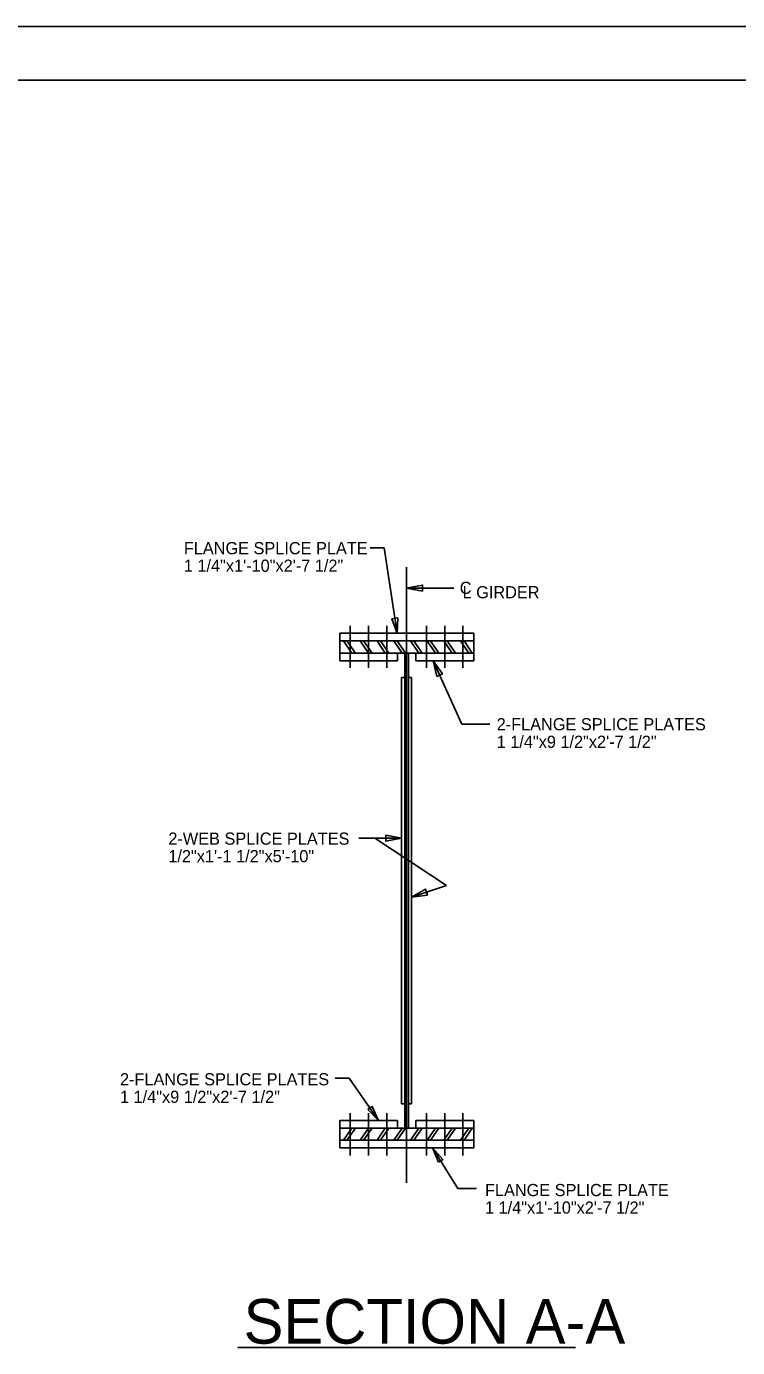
# Model space of a CAD drawing. Extents: x 1970675.2 to 1970715, y 796143 to 796167.2.
# Drawn here: x 1970685.62 to 1970692.92, y 796153.69 to 796167.25 of the extents above; entities that cross this region are included whole.
import ezdxf

# ---------------------------------------------------------------- set-up
doc = ezdxf.new("R2010")
doc.units = 0
for name, color, linetype in [('BR_AUTO DIMENSION', 7, 'Continuous'), ('BR_BORDER LINES', 7, 'Continuous'), ('BR_CENTER LINES', 7, 'Continuous'), ('BR_STRUCTURAL STEEL', 7, 'Continuous'), ('BR_TEXT', 7, 'Continuous'), ('Level 31', 7, 'Continuous')]:
    doc.layers.add(name, color=color, linetype=linetype)

msp = doc.modelspace()

# ---------------------------------------------------------------- linework, layer by layer
at = {"layer": 'BR_AUTO DIMENSION'}
for p, q in [((1970689.15, 796161.895), (1970689.296, 796161.895)), ((1970689.296, 796161.895), (1970689.428, 796161.018)), ((1970690.091, 796160.085), (1970689.798, 796160.736)), ((1970690.377, 796160.085), (1970690.091, 796160.085)), ((1970689.034, 796158.915), (1970689.474, 796158.915)), ((1970689.2, 796158.915), (1970689.934, 796158.429)), ((1970689.934, 796158.429), (1970689.576, 796158.31)), ((1970688.791, 796156.451), (1970688.937, 796156.451)), ((1970688.937, 796156.451), (1970689.238, 796156.018)), ((1970690.05, 796155.32), (1970689.791, 796155.736)), ((1970690.242, 796155.32), (1970690.05, 796155.32))]:
    msp.add_line(p, q, dxfattribs=at)
for points in [[(1970689.688, 796161.449), (1970689.525, 796161.48), (1970689.688, 796161.512)], [(1970689.434, 796161.176), (1970689.428, 796161.018), (1970689.374, 796161.167)], [(1970689.836, 796160.575), (1970689.798, 796160.736), (1970689.893, 796160.601)], [(1970689.312, 796158.946), (1970689.474, 796158.915), (1970689.312, 796158.884)], [(1970689.74, 796158.331), (1970689.576, 796158.31), (1970689.72, 796158.391)], [(1970689.128, 796156.131), (1970689.17, 796156.161), (1970689.238, 796156.018)], [(1970689.852, 796155.59), (1970689.896, 796155.617), (1970689.791, 796155.736)]]:
    msp.add_lwpolyline(points, close=True, dxfattribs=at)
msp.add_lwpolyline([(1970689.525, 796161.48), (1970690.011, 796161.48)], dxfattribs=at)
at = {"layer": 'BR_BORDER LINES'}
msp.add_line((1970714.286, 796166.696), (1970677.253, 796166.696), dxfattribs=at)
at = {"layer": 'BR_CENTER LINES'}
msp.add_line((1970689.525, 796161.698), (1970689.525, 796155.379), dxfattribs=at)
at = {"layer": 'BR_STRUCTURAL STEEL'}
for p, q in [((1970688.838, 796161.018), (1970690.213, 796161.018)), ((1970688.838, 796160.94), (1970688.838, 796161.018)), ((1970688.947, 796160.663), (1970688.947, 796161.095)), ((1970689.135, 796160.663), (1970689.135, 796161.095)), ((1970689.322, 796160.663), (1970689.322, 796161.095)), ((1970689.728, 796160.663), (1970689.728, 796161.095)), ((1970689.916, 796160.663), (1970689.916, 796161.095)), ((1970690.103, 796160.663), (1970690.103, 796161.095)), ((1970690.213, 796161.018), (1970690.213, 796160.94)), ((1970688.838, 796160.815), (1970688.838, 796160.94)), ((1970690.213, 796160.94), (1970688.838, 796160.94)), ((1970688.838, 796160.94), (1970690.213, 796160.94)), ((1970688.878, 796160.94), (1970688.963, 796160.815)), ((1970688.913, 796160.94), (1970688.999, 796160.815)), ((1970689.049, 796160.94), (1970689.135, 796160.815)), ((1970689.084, 796160.94), (1970689.17, 796160.815)), ((1970689.221, 796160.94), (1970689.306, 796160.815)), ((1970689.256, 796160.94), (1970689.342, 796160.815)), ((1970689.392, 796160.94), (1970689.478, 796160.815)), ((1970689.427, 796160.94), (1970689.513, 796160.815)), ((1970689.563, 796160.94), (1970689.649, 796160.815)), ((1970689.599, 796160.94), (1970689.684, 796160.815)), ((1970689.735, 796160.94), (1970689.821, 796160.815)), ((1970689.77, 796160.94), (1970689.856, 796160.815)), ((1970689.906, 796160.94), (1970689.992, 796160.815)), ((1970689.942, 796160.94), (1970690.027, 796160.815)), ((1970690.079, 796160.94), (1970690.164, 796160.815)), ((1970690.114, 796160.94), (1970690.199, 796160.815)), ((1970690.213, 796160.815), (1970690.213, 796160.94)), ((1970688.838, 796160.815), (1970690.213, 796160.815)), ((1970688.838, 796160.815), (1970688.838, 796160.736)), ((1970689.431, 796160.815), (1970688.838, 796160.815)), ((1970688.838, 796160.736), (1970689.431, 796160.736)), ((1970689.431, 796160.815), (1970689.431, 796160.736)), ((1970689.506, 796160.815), (1970689.506, 796155.94)), ((1970689.545, 796160.815), (1970689.545, 796155.94)), ((1970689.619, 796160.815), (1970690.213, 796160.815)), ((1970689.619, 796160.815), (1970689.619, 796160.736)), ((1970690.213, 796160.736), (1970689.619, 796160.736)), ((1970690.213, 796160.815), (1970690.213, 796160.736)), ((1970689.506, 796160.565), (1970689.474, 796160.565)), ((1970689.474, 796160.565), (1970689.474, 796156.19)), ((1970689.506, 796156.19), (1970689.506, 796160.565)), ((1970689.545, 796156.19), (1970689.545, 796160.565)), ((1970689.576, 796160.565), (1970689.545, 796160.565)), ((1970689.576, 796160.565), (1970689.576, 796156.19)), ((1970689.506, 796156.19), (1970689.474, 796156.19)), ((1970689.576, 796156.19), (1970689.545, 796156.19)), ((1970688.838, 796155.94), (1970688.838, 796156.018)), ((1970688.838, 796156.018), (1970689.431, 796156.018)), ((1970688.947, 796156.091), (1970688.947, 796155.659)), ((1970689.135, 796156.091), (1970689.135, 796155.659)), ((1970689.322, 796156.091), (1970689.322, 796155.659)), ((1970689.431, 796155.94), (1970689.431, 796156.018)), ((1970690.213, 796156.018), (1970689.619, 796156.018)), ((1970689.619, 796155.94), (1970689.619, 796156.018)), ((1970689.728, 796156.091), (1970689.728, 796155.659)), ((1970689.916, 796156.091), (1970689.916, 796155.659)), ((1970690.103, 796156.091), (1970690.103, 796155.659)), ((1970690.213, 796155.94), (1970690.213, 796156.018)), ((1970688.838, 796155.94), (1970690.213, 796155.94)), ((1970688.838, 796155.94), (1970688.838, 796155.815)), ((1970689.431, 796155.94), (1970688.838, 796155.94)), ((1970688.878, 796155.815), (1970688.963, 796155.94)), ((1970688.913, 796155.815), (1970688.999, 796155.94)), ((1970689.049, 796155.815), (1970689.135, 796155.94)), ((1970689.084, 796155.815), (1970689.17, 796155.94)), ((1970689.221, 796155.815), (1970689.306, 796155.94)), ((1970689.256, 796155.815), (1970689.342, 796155.94)), ((1970689.392, 796155.815), (1970689.478, 796155.94)), ((1970689.427, 796155.815), (1970689.513, 796155.94)), ((1970689.563, 796155.815), (1970689.649, 796155.94)), ((1970689.599, 796155.815), (1970689.684, 796155.94)), ((1970689.619, 796155.94), (1970690.213, 796155.94)), ((1970689.735, 796155.815), (1970689.821, 796155.94)), ((1970689.77, 796155.815), (1970689.856, 796155.94)), ((1970689.906, 796155.815), (1970689.992, 796155.94)), ((1970689.942, 796155.815), (1970690.027, 796155.94)), ((1970690.079, 796155.815), (1970690.164, 796155.94)), ((1970690.114, 796155.815), (1970690.199, 796155.94)), ((1970690.213, 796155.94), (1970690.213, 796155.815)), ((1970690.213, 796155.815), (1970688.838, 796155.815)), ((1970688.838, 796155.815), (1970690.213, 796155.815)), ((1970688.838, 796155.815), (1970688.838, 796155.736)), ((1970688.838, 796155.736), (1970690.213, 796155.736)), ((1970690.213, 796155.736), (1970690.213, 796155.815))]:
    msp.add_line(p, q, dxfattribs=at)
at = {"layer": 'BR_TEXT'}
msp.add_line((1970687.792, 796153.687), (1970691.258, 796153.687), dxfattribs=at)
at = {"layer": 'Level 31'}
msp.add_line((1970714.836, 796167.246), (1970675.236, 796167.246), dxfattribs=at)

# ---------------------------------------------------------------- texts
at = {"layer": 'BR_TEXT'}
for s, height, p in [('FLANGE SPLICE PLATE', 0.125, (1970687.239, 796161.829)), ('1 1/4"x1\'-10"x2\'-7 1/2"', 0.125, (1970687.239, 796161.649)), ('C', 0.125, (1970690.07, 796161.422)), ('L GIRDER', 0.125, (1970690.099, 796161.377)), ('2-FLANGE SPLICE PLATES', 0.125, (1970690.449, 796160.022)), ('1 1/4"x9 1/2"x2\'-7 1/2"', 0.125, (1970690.449, 796159.842)), ('2-WEB SPLICE PLATES', 0.125, (1970687.08, 796158.848)), ('1/2"x1\'-1 1/2"x5\'-10"', 0.125, (1970687.08, 796158.668)), ('2-FLANGE SPLICE PLATES', 0.125, (1970686.584, 796156.378)), ('1 1/4"x9 1/2"x2\'-7 1/2"', 0.125, (1970686.584, 796156.198)), ('FLANGE SPLICE PLATE', 0.125, (1970690.329, 796155.241)), ('1 1/4"x1\'-10"x2\'-7 1/2"', 0.125, (1970690.329, 796155.061)), ('SECTION A-A', 0.45834, (1970687.852, 796153.727))]:
    msp.add_text(s, height=height, dxfattribs=at).set_placement(p)

doc.saveas('drawing.dxf')
